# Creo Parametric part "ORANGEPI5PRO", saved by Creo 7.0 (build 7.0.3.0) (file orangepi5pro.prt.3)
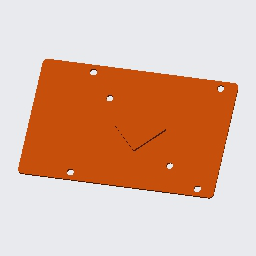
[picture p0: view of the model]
Units: millimeter Kilogram Sec (mmKs); MM, KILOGRAM, SECS

Created from: XX_SOLID_PART_MMKS_ABS.PRT

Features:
  1. coordinate system
  2. datum plane "RIGHT"
  3. datum plane "TOP"
  4. datum plane "FRONT"
  5. extrusion "Extrude 1"
  6. extruded cut "Extrude 2"
  7. extruded cut "Extrude 3"
  8. extrusion "Extrude 4"

Surfaces: 11 plane, 10 cylinder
